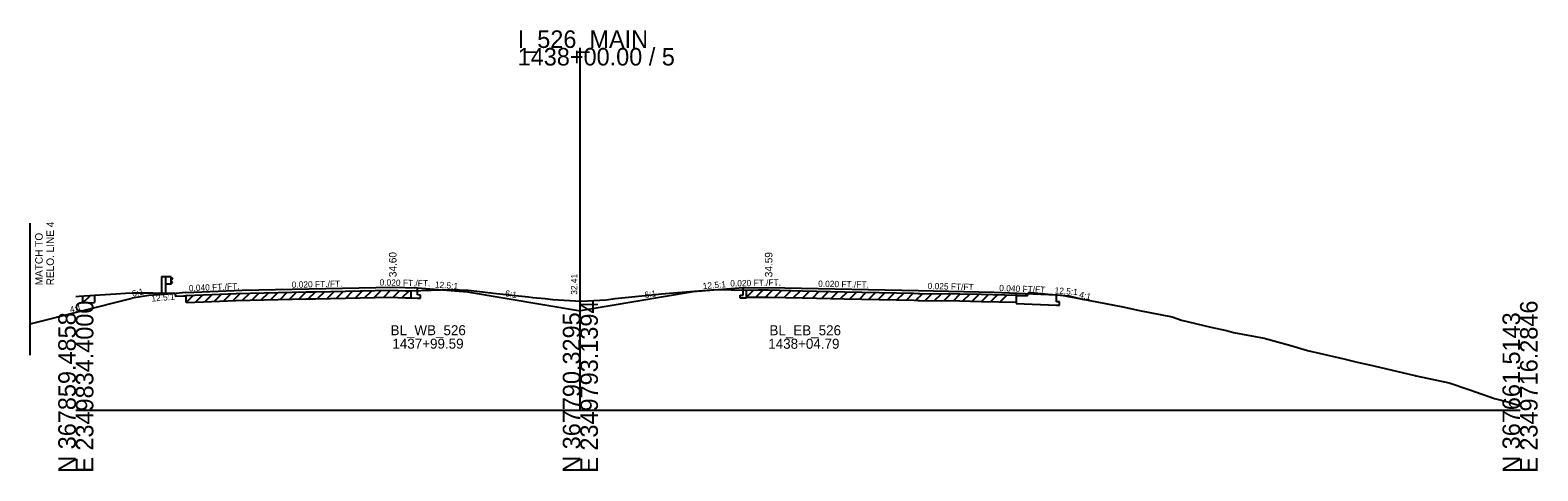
# Model space of a CAD drawing. Extents: x -170 to 2527928, y -10 to 1619750.
# Drawn here: x 4992.7 to 5233.4, y 2990.3 to 3060.6 of the extents above; entities that cross this region are included whole.
import ezdxf

# ---------------------------------------------------------------- set-up
doc = ezdxf.new("R2010")
doc.units = 0
for name, color, linetype in [('RD_GPK_XS_Cell', 7, 'Continuous'), ('RD_XS_Base', 7, 'Continuous'), ('RD_XS_EarthShd', 7, 'Continuous'), ('RD_XS_ExGround', 7, 'Continuous'), ('RD_XS_ExPaveRet', 7, 'Continuous'), ('RD_XS_GR', 7, 'Continuous'), ('RD_XS_MatchLine', 7, 'Continuous'), ('RD_XS_Pave', 7, 'Continuous'), ('RD_XS_PaveShd', 7, 'Continuous'), ('RD_XS_TieSlope', 7, 'Continuous'), ('RD_XS_TX_Elev_EX', 7, 'Continuous'), ('RD_XS_TX_Slope', 7, 'Continuous'), ('RD_XS_TX_Station', 7, 'Continuous')]:
    doc.layers.add(name, color=color, linetype=linetype)

msp = doc.modelspace()

# ---------------------------------------------------------------- linework, layer by layer
at = {"layer": 'RD_GPK_XS_Cell'}
for p, q in [((5080.53, 3000), (5080.53, 3057.8)), ((5000, 3000), (5080.53, 3000)), ((5080.53, 3000), (5230.53, 3000))]:
    msp.add_line(p, q, dxfattribs=at)
at = {"layer": 'RD_XS_Base'}
for p, q in [((5053.49, 3017.92), (5053.49, 3017.9)), ((5053.49, 3017.9), (5054.53, 3017.88)), ((5054.53, 3018.38), (5054.53, 3019.52)), ((5055.03, 3018.37), (5054.53, 3018.38)), ((5054.53, 3017.88), (5055.03, 3017.87)), ((5055.03, 3017.87), (5055.03, 3018.37)), ((5106.03, 3018.36), (5106.53, 3018.37)), ((5106.03, 3017.86), (5106.03, 3018.36)), ((5107.07, 3017.88), (5106.03, 3017.86)), ((5106.53, 3018.37), (5106.53, 3019.51)), ((5107.07, 3017.88), (5107.07, 3019.16)), ((5150.1, 3018.67), (5150.1, 3017.03)), ((5156.53, 3017.27), (5156.53, 3018.41)), ((5150.1, 3017.03), (5156.53, 3016.77)), ((5157.03, 3017.26), (5156.53, 3017.27)), ((5156.53, 3016.77), (5157.03, 3016.76)), ((5157.03, 3016.76), (5157.03, 3017.26))]:
    msp.add_line(p, q, dxfattribs=at)
at = {"layer": 'RD_XS_EarthShd'}
for p, q in [((5015.41, 3018.58), (5011.66, 3018.28)), ((5017.57, 3018.76), (5015.41, 3018.58)), ((5054.53, 3019.52), (5062.53, 3018.88)), ((5106.53, 3019.51), (5098.53, 3018.87))]:
    msp.add_line(p, q, dxfattribs=at)
at = {"layer": 'RD_XS_ExGround'}
msp.add_lwpolyline([(5000, 3018.15), (5000.54, 3018.18), (5002.99, 3018.33), (5006.36, 3018.54), (5007.92, 3018.68), (5009.16, 3018.74), (5010.65, 3018.72), (5012.3, 3018.7), (5015.38, 3018.67), (5015.7, 3018.65), (5015.77, 3018.65), (5015.89, 3018.3), (5015.92, 3018.21), (5017.18, 3018.23), (5017.46, 3018.25), (5017.57, 3018.29), (5017.6, 3018.3), (5020.4, 3018.41), (5025.61, 3018.63), (5036.78, 3018.87), (5037.7, 3018.89), (5038.24, 3018.9), (5050.17, 3019.12), (5052.64, 3019.06), (5053.49, 3019.05), (5059.98, 3019.27), (5062.64, 3019.16), (5064.91, 3018.89), (5066.67, 3018.68), (5070.65, 3018.26), (5072.23, 3018.06), (5072.94, 3017.98), (5074.9, 3017.8), (5076.16, 3017.67), (5080.66, 3017.41), (5084.65, 3017.59), (5086.08, 3017.79), (5093.01, 3018.51), (5093.51, 3018.55), (5094.14, 3018.63), (5100.06, 3019.11), (5102.14, 3019.23), (5107.07, 3019.16), (5108.99, 3019.17), (5110.51, 3019.17), (5115.99, 3019.04), (5122.68, 3018.9), (5133.76, 3018.64), (5134.45, 3018.63), (5134.69, 3018.63), (5141.08, 3018.55), (5144.53, 3018.49), (5150.1, 3018.37), (5150.18, 3018.34), (5150.3, 3018.29), (5151.01, 3018.3), (5151.91, 3018.29), (5151.99, 3018.51), (5152.09, 3018.78), (5152.26, 3018.78), (5152.49, 3018.79), (5155.23, 3018.53), (5157.31, 3018.36), (5160.46, 3017.75), (5167.11, 3016.46), (5169.81, 3015.89), (5175.01, 3014.9), (5176.5, 3014.38), (5181.19, 3013.24), (5183.68, 3012.73), (5184.8, 3012.36), (5189.69, 3011.48), (5193.96, 3010.31), (5196.6, 3009.51), (5202.4, 3008.17), (5204.54, 3007.67), (5206.49, 3007.24), (5213.52, 3005.57), (5213.79, 3005.51), (5213.88, 3005.48), (5213.95, 3005.47), (5219.23, 3004.37), (5222.51, 3003.24), (5226.46, 3001.85), (5228.72, 3001.27), (5230.53, 3000.7)], dxfattribs=at)
at = {"layer": 'RD_XS_ExPaveRet'}
for p, q in [((5001.13, 3017.1), (5002.32, 3018.29)), ((5001.13, 3017.1), (5001.13, 3018.22)), ((5002.99, 3018.33), (5002.99, 3017.2)), ((5017.6, 3017.18), (5018.77, 3018.35)), ((5017.6, 3017.18), (5017.6, 3018.3)), ((5019.1, 3017.24), (5020.27, 3018.4)), ((5020.6, 3017.3), (5021.77, 3018.47)), ((5022.1, 3017.36), (5023.27, 3018.53)), ((5023.6, 3017.42), (5024.77, 3018.59)), ((5025.1, 3017.48), (5026.26, 3018.64)), ((5026.6, 3017.53), (5027.75, 3018.67)), ((5028.1, 3017.56), (5029.25, 3018.71)), ((5029.6, 3017.59), (5030.75, 3018.74)), ((5031.1, 3017.62), (5032.25, 3018.77)), ((5032.6, 3017.66), (5033.75, 3018.8)), ((5034.1, 3017.69), (5035.25, 3018.84)), ((5035.6, 3017.72), (5036.75, 3018.87)), ((5037.1, 3017.76), (5038.24, 3018.9)), ((5038.24, 3017.78), (5050.17, 3018)), ((5038.6, 3017.79), (5039.74, 3018.93)), ((5040.1, 3017.81), (5041.24, 3018.95)), ((5041.6, 3017.84), (5042.74, 3018.98)), ((5043.1, 3017.87), (5044.24, 3019.01)), ((5044.6, 3017.89), (5045.74, 3019.04)), ((5046.1, 3017.92), (5047.24, 3019.06)), ((5047.6, 3017.95), (5048.74, 3019.09)), ((5049.1, 3017.98), (5050.24, 3019.12)), ((5050.17, 3018), (5052.64, 3017.94)), ((5050.6, 3017.99), (5051.7, 3019.08)), ((5052.1, 3017.95), (5053.2, 3019.05)), ((5052.64, 3017.94), (5053.49, 3017.92)), ((5053.49, 3019.05), (5053.49, 3017.92)), ((5107.07, 3018.04), (5108.2, 3019.17)), ((5107.07, 3018.04), (5107.07, 3019.16)), ((5107.07, 3018.04), (5108.99, 3018.05)), ((5108.57, 3018.05), (5109.7, 3019.17)), ((5108.99, 3018.05), (5110.51, 3018.05)), ((5110.07, 3018.05), (5111.18, 3019.16)), ((5110.51, 3018.05), (5115.99, 3017.92)), ((5111.57, 3018.03), (5112.67, 3019.12)), ((5113.07, 3017.99), (5114.17, 3019.09)), ((5114.57, 3017.96), (5115.67, 3019.05)), ((5115.99, 3017.92), (5122.68, 3017.78)), ((5116.07, 3017.92), (5117.17, 3019.02)), ((5117.57, 3017.89), (5118.67, 3018.99)), ((5119.07, 3017.86), (5120.17, 3018.96)), ((5120.57, 3017.83), (5121.67, 3018.92)), ((5122.07, 3017.79), (5123.17, 3018.89)), ((5123.57, 3017.76), (5124.67, 3018.86)), ((5125.07, 3017.73), (5126.17, 3018.82)), ((5126.57, 3017.69), (5127.67, 3018.79)), ((5128.07, 3017.66), (5129.17, 3018.75)), ((5129.57, 3017.62), (5130.67, 3018.72)), ((5131.07, 3017.59), (5132.17, 3018.68)), ((5132.57, 3017.55), (5133.67, 3018.65)), ((5134.07, 3017.52), (5135.18, 3018.62)), ((5135.57, 3017.49), (5136.68, 3018.6)), ((5137.07, 3017.48), (5138.18, 3018.58)), ((5138.57, 3017.46), (5139.68, 3018.57)), ((5140.07, 3017.44), (5141.18, 3018.55)), ((5141.57, 3017.42), (5142.68, 3018.52)), ((5143.07, 3017.39), (5144.18, 3018.49)), ((5144.57, 3017.36), (5145.67, 3018.46)), ((5146.07, 3017.33), (5147.17, 3018.43)), ((5147.57, 3017.3), (5148.67, 3018.4)), ((5150.1, 3018.37), (5150.1, 3017.25)), ((5001.13, 3017.1), (5002.99, 3017.2)), ((5017.6, 3017.18), (5020.4, 3017.29)), ((5020.4, 3017.29), (5025.61, 3017.5)), ((5025.61, 3017.5), (5036.78, 3017.75)), ((5036.78, 3017.75), (5037.7, 3017.77)), ((5037.7, 3017.77), (5038.24, 3017.78)), ((5122.68, 3017.78), (5133.76, 3017.52)), ((5133.76, 3017.52), (5134.45, 3017.51)), ((5134.45, 3017.51), (5134.69, 3017.51)), ((5134.69, 3017.51), (5141.08, 3017.43)), ((5141.08, 3017.43), (5144.53, 3017.36)), ((5144.53, 3017.36), (5150.1, 3017.25))]:
    msp.add_line(p, q, dxfattribs=at)
at = {"layer": 'RD_XS_GR'}
for p, q in [((5014.33, 3021.26), (5013.66, 3021.26)), ((5013.66, 3021.26), (5013.66, 3018.47)), ((5015.24, 3021.26), (5014.33, 3021.26)), ((5014.33, 3021.26), (5014.33, 3018.52)), ((5015.24, 3020.1), (5015.24, 3021.26)), ((5015.24, 3021.19), (5015.41, 3020.99)), ((5015.41, 3020.94), (5015.24, 3020.74)), ((5015.41, 3020.42), (5015.24, 3020.62)), ((5015.24, 3020.17), (5015.41, 3020.37)), ((5015.41, 3020.99), (5015.41, 3020.94)), ((5015.41, 3020.37), (5015.41, 3020.42)), ((5015.24, 3020.1), (5014.33, 3020.1))]:
    msp.add_line(p, q, dxfattribs=at)
at = {"layer": 'RD_XS_MatchLine'}
msp.add_line((4992.71, 3008.77), (4992.71, 3029.83), dxfattribs=at)
at = {"layer": 'RD_XS_Pave'}
for p, q in [((5026.53, 3019.12), (5050.53, 3019.6)), ((5110.53, 3019.59), (5134.53, 3019.11)), ((5134.53, 3019.11), (5146.53, 3018.81))]:
    msp.add_line(p, q, dxfattribs=at)
at = {"layer": 'RD_XS_PaveShd'}
for p, q in [((5017.57, 3018.76), (5026.53, 3019.12)), ((5050.53, 3019.6), (5054.53, 3019.52)), ((5106.53, 3019.51), (5110.53, 3019.59)), ((5146.53, 3018.81), (5156.53, 3018.41))]:
    msp.add_line(p, q, dxfattribs=at)
at = {"layer": 'RD_XS_TieSlope'}
for p, q in [((5011.66, 3018.28), (5009.01, 3017.84)), ((5062.53, 3018.88), (5080.56, 3015.87)), ((5098.53, 3018.87), (5080.56, 3015.87)), ((5156.53, 3018.41), (5158.53, 3018.25)), ((5158.53, 3018.25), (5160.84, 3017.67)), ((4992.71, 3013.77), (5009.01, 3017.84))]:
    msp.add_line(p, q, dxfattribs=at)

# ---------------------------------------------------------------- texts
at = {"layer": 'RD_GPK_XS_Cell'}
for s, p in [('I_526_MAIN', (5070.53, 3057.8)), ('1438+00.00 / 5', (5070.53, 3055))]:
    msp.add_text(s, height=2.8, dxfattribs=at).set_placement(p)
for s, p in [('E 2349834.4000', (5002.8, 2990)), ('E 2349793.1394', (5083.33, 2990)), ('E 2349716.2846', (5233.33, 2990)), ('N 367859.4858', (5000, 2990)), ('N 367790.3295', (5080.53, 2990)), ('N 367661.5143', (5230.53, 2990))]:
    msp.add_text(s, height=2.8, rotation=90, dxfattribs=at).set_placement(p)
at = {"layer": 'RD_XS_TX_Elev_EX'}
msp.add_text('32.41', height=1, rotation=90, dxfattribs=at).set_placement((5080.03, 3018.41))
at = {"layer": 'RD_XS_TX_Slope'}
for s, rotation, p in [('0.020 FT./FT.', 1.1458, (5034.47, 3019.52)), ('0.020 FT./FT.', 358.8542, (5048.48, 3019.89)), ('12.5:1', 355.4261, (5057.28, 3019.56)), ('12.5:1', 4.5739, (5100.11, 3019.31)), ('0.020 FT./FT.', 1.1458, (5104.47, 3019.72)), ('0.020 FT./FT.', 358.8542, (5118.48, 3019.68)), ('0.025 FT/FT', 358.5679, (5135.95, 3019.32)), ('6:1', 12.4816, (5009.08, 3018.08)), ('12.5:1', 4.5739, (5012.1, 3017.31)), ('0.040 FT./FT.', 2.2906, (5018.06, 3018.96)), ('6:1', 350.5377, (5068.47, 3018.18)), ('6:1', 9.4623, (5090.86, 3017.88)), ('0.040 FT/FT', 357.7094, (5147.38, 3019)), ('12.5:1', 355.4261, (5156.2, 3018.63)), ('4:1', 346.8379, (5160.09, 3017.99)), ('4:1', 13.8739, (4999.17, 3015.51))]:
    msp.add_text(s, height=1, rotation=rotation, dxfattribs=at).set_placement(p)
at = {"layer": 'RD_XS_TX_Station'}
for s, p in [('RELO. LINE 4', (4996.51, 3019.92)), ('MATCH TO', (4994.71, 3019.92)), (' 34.60', (5051.19, 3020.77)), (' 34.59', (5111.19, 3020.76))]:
    msp.add_text(s, height=1.2, rotation=90, dxfattribs=at).set_placement(p)
for s, p in [('BL_WB_526', (5050.24, 3011.95)), ('BL_EB_526', (5110.72, 3011.94)), ('1437+99.59', (5050.53, 3009.8)), ('1438+04.79', (5110.53, 3009.79))]:
    msp.add_text(s, height=1.6, dxfattribs=at).set_placement(p)

doc.saveas('drawing.dxf')
